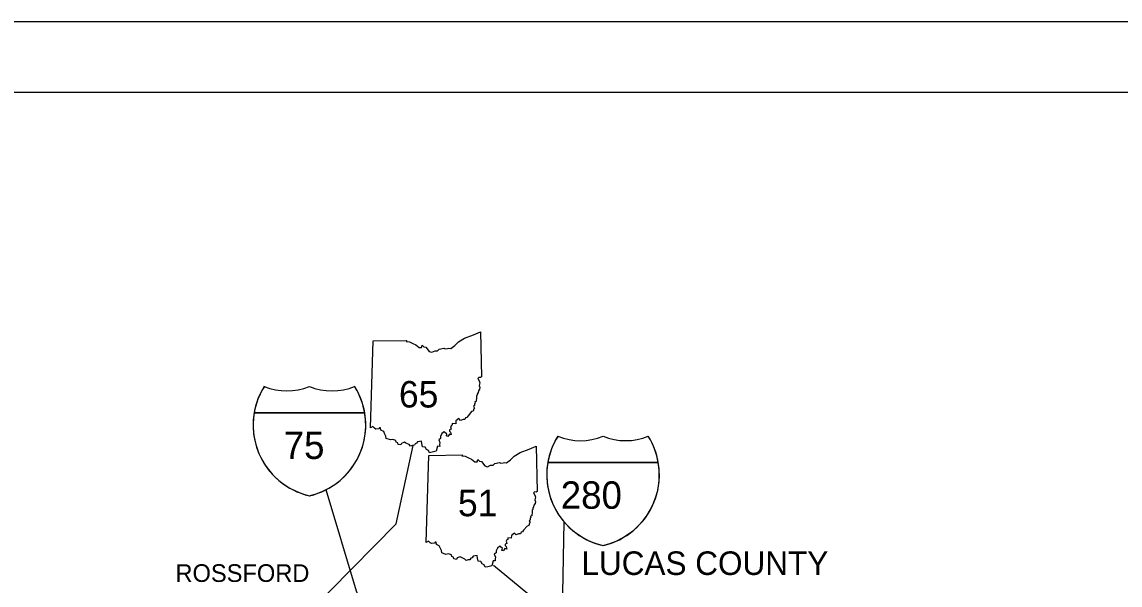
# Model space of a CAD drawing. Extents: x 0 to 851, y 0 to 440.
# Drawn here: x 318.5 to 474.6, y 359.9 to 440 of the extents above; entities that cross this region are included whole.
import ezdxf

# ---------------------------------------------------------------- set-up
doc = ezdxf.new("R2010")
doc.units = 0
for name, color, linetype in [('GM_X_Adjacent_County_Text', 7, 'Continuous'), ('GM_X_Corporation_Text', 7, 'Continuous'), ('GM_X_Interstate_Route', 7, 'Continuous'), ('GM_X_State_Route', 7, 'Continuous'), ('PV_P_Text', 7, 'Continuous'), ('SH_Border', 7, 'Continuous'), ('SH_Cut_Line', 7, 'Continuous')]:
    doc.layers.add(name, color=color, linetype=linetype)

msp = doc.modelspace()

# ---------------------------------------------------------------- linework, layer by layer
at = {"layer": 'GM_X_Interstate_Route'}
for points in [[(366.26, 358.51), (366.16, 358.81), (366.07, 359.07), (361.74, 373.46)], [(395.33, 354.4), (395.34, 354.94), (395.35, 355.45), (395.36, 355.98), (395.37, 356.54), (395.37, 357.35), (395.39, 358.05), (395.39, 358.09), (395.4, 358.76), (395.6, 368.88)]]:
    msp.add_lwpolyline(points, dxfattribs=at)
at = {"layer": 'GM_X_State_Route'}
msp.add_line((371.72, 368.62), (374.09, 379.78), dxfattribs=at)
for points in [[(360.65, 357.45), (360.92, 357.72), (361.19, 358.01), (361.46, 358.29), (361.8, 358.61), (362.09, 358.89), (362.31, 359.12), (371.72, 368.62)], [(385.51, 362.74), (391.2, 358.09), (390.84, 358.4), (390.82, 358.42)]]:
    msp.add_lwpolyline(points, dxfattribs=at)
at = {"layer": 'PV_P_Text'}
for p, q in [((368.07, 382.27), (368.42, 394.64)), ((351.51, 384.42), (367.23, 384.42)), ((367.23, 384.42), (351.51, 384.42)), ((367.23, 384.42), (351.51, 384.42)), ((375.98, 366), (376.32, 378.37)), ((375.98, 366), (376.32, 378.37)), ((393.25, 377.34), (408.97, 377.34)), ((408.97, 377.34), (393.25, 377.34)), ((408.97, 377.34), (393.25, 377.34))]:
    msp.add_line(p, q, dxfattribs=at)
for points in [[(368.42, 394.64), (373.22, 394.72), (373.14, 394.57), (373.6, 394.54), (374.08, 394.28), (374.48, 394.11), (374.98, 393.71), (375.28, 393.72), (375.41, 394.04), (375.63, 393.79), (375.9, 393.75), (376.37, 393.16), (376.76, 393.03), (377.22, 393.23), (377.57, 393.26), (377.82, 393.46), (378.48, 393.64), (378.66, 393.53), (379.01, 393.55), (379.19, 393.63), (379.49, 393.56), (380.03, 394.01), (380.58, 394.54), (381.43, 395.04), (382.69, 395.52), (383.69, 395.94), (383.84, 389.52)], [(383.84, 389.52), (383.69, 389.43), (383.46, 389.47), (383.31, 389.29), (383.5, 388.99), (383.59, 388.68), (383.51, 388.33), (383.59, 388.04), (383.53, 387.8), (383.39, 387.56), (383.34, 387.33), (383.22, 387.08), (383.23, 386.95), (383.11, 386.84), (383.13, 386.44), (383.07, 386.22), (383.09, 386.03), (382.9, 385.98), (382.94, 385.82), (382.82, 385.69), (382.85, 385.48), (382.71, 385.35), (382.85, 385.08), (382.74, 384.99), (382.65, 384.67), (382.41, 384.6), (381.92, 384), (381.75, 383.78), (381.55, 383.72), (381.44, 383.49), (381.21, 383.48), (380.85, 383.32), (380.61, 383.6), (380.2, 383.27), (380.16, 382.88), (379.64, 382.89), (379.66, 382.7), (379.55, 382.64), (379.44, 382.45), (379.5, 382.1), (379.26, 382.01), (379.29, 381.81), (379.44, 381.69), (379.51, 381.3), (379.26, 381.38), (379.05, 381.05), (378.83, 381.13), (378.9, 381.41), (378.53, 381.74), (378.19, 381.47), (378.01, 381.05), (378.01, 380.76), (377.75, 380.59), (377.91, 380.19), (377.88, 379.91), (377.89, 379.65), (377.57, 379.66), (377.37, 378.95)], [(377.37, 378.95), (376.81, 378.81), (376.42, 378.73), (376.28, 379.05), (376.01, 379.22), (375.83, 379.55), (375.43, 379.59), (375.33, 380.04), (375.29, 380.4), (374.74, 380.31), (374.59, 380.09), (374.4, 380.03), (374.29, 379.81), (374.02, 379.79), (373.74, 379.68), (373.55, 379.9), (373.09, 380.12), (372.88, 380.23), (372.44, 380.06), (372.35, 379.85), (372, 379.94), (371.92, 380.17), (371.71, 380.24), (371.67, 380.49), (371.22, 380.62), (370.87, 380.57), (370.27, 380.77), (370.23, 381.09), (370.02, 381.49), (369.92, 381.76), (369.53, 381.97), (369.45, 382.3), (369.33, 382.29), (369.22, 382.16), (368.79, 382.09), (368.62, 382.23), (368.39, 382.46), (368.07, 382.27)], [(376.32, 378.37), (381.12, 378.45), (381.05, 378.3), (381.5, 378.27), (381.98, 378.01), (382.39, 377.84), (382.89, 377.45), (383.19, 377.45), (383.31, 377.77), (383.54, 377.53), (383.81, 377.48), (384.28, 376.89), (384.66, 376.76), (385.13, 376.96), (385.47, 377), (385.73, 377.2), (386.38, 377.37), (386.57, 377.27), (386.92, 377.29), (387.09, 377.36), (387.4, 377.3), (387.93, 377.75), (388.48, 378.28), (389.33, 378.78), (390.6, 379.25), (391.6, 379.67), (391.74, 373.25)], [(376.32, 378.37), (381.12, 378.45), (381.05, 378.3), (381.5, 378.27), (381.98, 378.01), (382.39, 377.84), (382.89, 377.45), (383.19, 377.45), (383.31, 377.77), (383.54, 377.53), (383.81, 377.48), (384.28, 376.89), (384.66, 376.76), (385.13, 376.96), (385.47, 377), (385.73, 377.2), (386.38, 377.37), (386.57, 377.27), (386.92, 377.29), (387.09, 377.36), (387.4, 377.3), (387.93, 377.75), (388.48, 378.28), (389.33, 378.78), (390.6, 379.25), (391.6, 379.67), (391.74, 373.25)], [(391.74, 373.25), (391.6, 373.16), (391.37, 373.21), (391.21, 373.03), (391.4, 372.73), (391.49, 372.41), (391.41, 372.06), (391.49, 371.77), (391.44, 371.53), (391.29, 371.29), (391.24, 371.06), (391.12, 370.82), (391.13, 370.68), (391.01, 370.58), (391.03, 370.17), (390.98, 369.95), (391, 369.76), (390.81, 369.71), (390.85, 369.55), (390.73, 369.43), (390.75, 369.22), (390.62, 369.08), (390.75, 368.81), (390.64, 368.73), (390.55, 368.4), (390.31, 368.33), (389.82, 367.73), (389.65, 367.51), (389.46, 367.45), (389.35, 367.22), (389.11, 367.22), (388.75, 367.06), (388.52, 367.33), (388.11, 367), (388.06, 366.61), (387.55, 366.63), (387.57, 366.43), (387.45, 366.37), (387.35, 366.18), (387.41, 365.83), (387.17, 365.74), (387.19, 365.54), (387.35, 365.42), (387.42, 365.03), (387.16, 365.11), (386.95, 364.79), (386.73, 364.86), (386.81, 365.14), (386.44, 365.47), (386.09, 365.2), (385.91, 364.78), (385.91, 364.5), (385.65, 364.32), (385.82, 363.92), (385.79, 363.64), (385.79, 363.38), (385.47, 363.39), (385.28, 362.68)], [(391.74, 373.25), (391.6, 373.16), (391.37, 373.21), (391.21, 373.03), (391.4, 372.73), (391.49, 372.41), (391.41, 372.06), (391.49, 371.77), (391.44, 371.53), (391.29, 371.29), (391.24, 371.06), (391.12, 370.82), (391.13, 370.68), (391.01, 370.58), (391.03, 370.17), (390.98, 369.95), (391, 369.76), (390.81, 369.71), (390.85, 369.55), (390.73, 369.43), (390.75, 369.22), (390.62, 369.08), (390.75, 368.81), (390.64, 368.73), (390.55, 368.4), (390.31, 368.33), (389.82, 367.73), (389.65, 367.51), (389.46, 367.45), (389.35, 367.22), (389.11, 367.22), (388.75, 367.06), (388.52, 367.33), (388.11, 367), (388.06, 366.61), (387.55, 366.63), (387.57, 366.43), (387.45, 366.37), (387.35, 366.18), (387.41, 365.83), (387.17, 365.74), (387.19, 365.54), (387.35, 365.42), (387.42, 365.03), (387.16, 365.11), (386.95, 364.79), (386.73, 364.86), (386.81, 365.14), (386.44, 365.47), (386.09, 365.2), (385.91, 364.78), (385.91, 364.5), (385.65, 364.32), (385.82, 363.92), (385.79, 363.64), (385.79, 363.38), (385.47, 363.39), (385.28, 362.68)], [(385.28, 362.68), (384.72, 362.54), (384.33, 362.46), (384.19, 362.79), (383.91, 362.96), (383.73, 363.28), (383.33, 363.33), (383.24, 363.77), (383.19, 364.13), (382.65, 364.04), (382.5, 363.82), (382.3, 363.76), (382.19, 363.54), (381.93, 363.52), (381.64, 363.42), (381.46, 363.63), (380.99, 363.85), (380.78, 363.97), (380.35, 363.79), (380.26, 363.58), (379.91, 363.68), (379.83, 363.91), (379.62, 363.98), (379.57, 364.22), (379.12, 364.36), (378.78, 364.3), (378.17, 364.5), (378.13, 364.83), (377.93, 365.22), (377.82, 365.49), (377.44, 365.7), (377.36, 366.03), (377.24, 366.02), (377.13, 365.89), (376.7, 365.83), (376.53, 365.96), (376.29, 366.19), (375.98, 366)], [(385.28, 362.68), (384.72, 362.54), (384.33, 362.46), (384.19, 362.79), (383.91, 362.96), (383.73, 363.28), (383.33, 363.33), (383.24, 363.77), (383.19, 364.13), (382.65, 364.04), (382.5, 363.82), (382.3, 363.76), (382.19, 363.54), (381.93, 363.52), (381.64, 363.42), (381.46, 363.63), (380.99, 363.85), (380.78, 363.97), (380.35, 363.79), (380.26, 363.58), (379.91, 363.68), (379.83, 363.91), (379.62, 363.98), (379.57, 364.22), (379.12, 364.36), (378.78, 364.3), (378.17, 364.5), (378.13, 364.83), (377.93, 365.22), (377.82, 365.49), (377.44, 365.7), (377.36, 366.03), (377.24, 366.02), (377.13, 365.89), (376.7, 365.83), (376.53, 365.96), (376.29, 366.19), (375.98, 366)]]:
    msp.add_lwpolyline(points, dxfattribs=at)
for centre, radius, start, end in [((361.69, 382.69), 10.33, 147.8216, 256.9941), ((361.05, 382.87), 9.66, 146.654, 170.759), ((356.16, 395.78), 8.24, 247.0848, 292.9105), ((356.16, 395.78), 8.24, 247.0848, 292.9105), ((357.04, 382.69), 10.33, 283.0065, 32.1787), ((362.58, 395.78), 8.24, 247.0916, 292.9084), ((362.58, 395.78), 8.24, 247.0916, 292.9084), ((357.04, 382.69), 10.33, 9.6475, 32.179), ((361.69, 382.69), 10.33, 170.3514, 256.9967), ((357.07, 382.69), 10.31, 282.7667, 9.6898), ((403.43, 375.61), 10.33, 147.8216, 256.9941), ((402.79, 375.79), 9.66, 146.654, 170.759), ((397.9, 388.7), 8.24, 247.0848, 292.9105), ((397.9, 388.7), 8.24, 247.0848, 292.9105), ((398.78, 375.61), 10.33, 283.0065, 32.1787), ((404.32, 388.71), 8.24, 247.0916, 292.9084), ((404.32, 388.71), 8.24, 247.0916, 292.9084), ((398.78, 375.61), 10.33, 9.6475, 32.179), ((403.43, 375.61), 10.33, 170.3514, 256.9967), ((398.8, 375.61), 10.31, 282.7667, 9.6898)]:
    msp.add_arc(centre, radius, start, end, dxfattribs=at)
at = {"layer": 'SH_Border'}
msp.add_lwpolyline([(30, 430), (670, 430), (670, 10), (30, 10)], close=True, dxfattribs=at)
at = {"layer": 'SH_Cut_Line'}
msp.add_lwpolyline([(0, 0), (680, 0), (680, 440), (0, 440)], close=True, dxfattribs=at)

# ---------------------------------------------------------------- texts
at = {"layer": 'GM_X_Adjacent_County_Text'}
msp.add_text('LUCAS COUNTY', height=3.35, dxfattribs=at).set_placement((398.03, 361.37))
at = {"layer": 'GM_X_Corporation_Text'}
msp.add_text('ROSSFORD', height=2.513, rotation=0, dxfattribs=at).set_placement((340.32, 360.38))
at = {"layer": 'PV_P_Text'}
for s, height, p in [('65', 3.769, (372.09, 385.18)), ('75', 3.901, (355.7, 377.86)), ('280', 3.901, (395.09, 370.78)), ('51', 3.769, (380.48, 369.72))]:
    msp.add_text(s, height=height, dxfattribs=at).set_placement(p)

doc.saveas('drawing.dxf')
